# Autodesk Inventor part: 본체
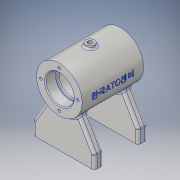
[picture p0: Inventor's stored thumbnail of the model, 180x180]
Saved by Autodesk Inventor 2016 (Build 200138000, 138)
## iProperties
Created: 2018-05
Part Number: 본체
Material: 알루미늄 6061
Document SubType Name: Modeling
Designer: USER
Density: 2.7 g/cm^3
Appearance: 알루미늄 - 평지
Mass: 317.681 g
Surface Area: 375.828 cm^2
Volume: 117.66 cm^3
Author: USER
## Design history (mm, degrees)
sketch "스케치1"
  geometry: L1 (0, 35)-(0, -35); L2 (26, 35)-(26, -35); L3 (26, -35)-(16, -35); L4 (16, -35)-(16, -23); L5 (16, -23)-(14, -23); L6 (14, -23)-(14, -21); L7 (14, -21)-(21, -21); L8 (21, -21)-(21, 21); L9 (21, 21)-(14, 21); L10 (14, 21)-(14, 23); L11 (14, 23)-(16, 23); L12 (16, 23)-(16, 35); L13 (16, 35)-(26, 35); 2 further points
  constraints: 26 end point, 9 perpendicular, 6 point on line, 2 vertical, 1 coincident, 1 midpoint
  dimensions: "d0" = 70 distance of L1.start L1.end; "d2" = 52 diameter of L2 L1; "d3" = 32 diameter of L12 L1; "d4" = 28 diameter of L10 L1; "d5" = 42 diameter of L8 L1; "d6" = 12 distance between parallel lines of L11 L13; "d7" = 12 distance between parallel lines of L3 L5; "d8" = 42 distance between parallel lines of L7 L9; "d9" = 2 distance between parallel lines of L9 L11
revolve "회전1" sketch "스케치1" stored, may be unused: angle "d10" = 90 deg
node "작업 평면1"
sketch "스케치2"
  geometry: L1 (-26, -35)-(26, -35) reference; L2 (-26, 35)-(26, 35) reference; C1 r 5 at (0, 0); 1 further point
  constraints: 1 centre point, 1 coincident
  dimensions: "d12" = 10 diameter of C1
extrude "돌출1" join sketch "스케치2" stored distance "d13" = 10; taper "d14" = 0 deg
sketch "스케치3"
  geometry: C1 r 5 at (0, 0) reference; 1 further point
  constraints: 1 coincident
hole "구멍1" sketch "스케치3" at (0, 0) diameter "d15" = 5.188; stored, may be unused: countersink angle "d19" = 90 deg, drill point angle "d21" = 118 deg; dims "d16" = 12, "d17" = 4, "d18" = 2, "d20" = 16
sketch "스케치4"
  geometry: L1 (0, 0)-(-9.919, -27.251); L2 (0, 0)-(29, 0); C1 r 26 at (0, 0) reference; 1 further point
  constraints: 4 end point, 1 equal length, 1 horizontal
  dimensions: "d22" = 29 distance of L1.start L1.end; "d23" = 110 deg angle of L1 L2
node "작업 평면2"
sketch "스케치5"
  geometry: C1 r 6 at (0, 0); 2 further points
  constraints: 1 centre point, 1 coincident
  dimensions: "d24" = 12 diameter of C1
extrude "돌출2" join sketch "스케치5" stored distance "d25" = 10; taper "d26" = 0 deg
sketch "스케치6"
  geometry: C1 r 6 at (0, 0) reference; 1 further point
  constraints: 1 coincident
hole "구멍2" sketch "스케치6" at (0, 0) diameter "d27" = 5.188; stored, may be unused: countersink angle "d31" = 90 deg, drill point angle "d33" = 118 deg; dims "d28" = 12, "d29" = 4, "d30" = 2, "d32" = 16
node "작업 평면3"
sketch "스케치7"
  geometry: L1 (-35, -65)-(35, -65); L2 (-35, -65)-(-35, -50); L3 (35, -65)-(35, -50); L4 (35, -50)-(17.325, -19.386); L5 (-35, -50)-(-17.325, -19.386); L6 (-35, -50)-(5.727, -50); A1 r 26 centre (0, 0) between (-17.325, -19.386) and (17.325, -19.386) reference; A2 r 26 centre (0, 0) between (-17.325, -19.386) and (17.325, -19.386); 2 further points
  constraints: 12 end point, 4 point on circle, 2 horizontal, 2 vertical, 1 centre point, 1 concentric, 1 midpoint, 1 vertical alignment
  dimensions: "d35" = 70 distance of L1.start L1.end; "d36" = 15 distance of L1.start L2.end; "d37" = 15 distance of L1.end L3.end; "d38" = 150 deg angle of L4 L3; "d39" = 60 deg angle of L6 L5; "d40" = 65 distance from line of point (0, 0) L1
extrude "돌출3" join sketch "스케치7" distance "d41" = 10; taper "d42" = 0 deg
sketch "스케치8" dims "d43" = 42
  geometry: C1 r 26 at (0, 0) reference; C2 r 16 at (0, 0) reference; 5 further points
  constraints: 2 vertical alignment, 1 coincident, 7 other
  dimensions: "d46" = 360 deg dimension on C1.centre point (0, 21) (derived)
hole "구멍3" sketch "스케치8" at (0, 21), (-21, 0), (0, -21), (21, 0) diameter "d48" = 3.242; stored, may be unused: countersink angle "d52" = 90 deg, drill point angle "d54" = 118 deg; dims "d49" = 8, "d50" = 4, "d51" = 2, "d53" = 10
sketch "스케치11"
  geometry: L1 (0, -60)-(70, -60) reference; L2 (70, -60)-(70, -50) reference; L3 (70, -50)-(0, -50) reference; L4 (0, -60)-(0, -50) reference; 5 further points
  dimensions: "d56" = 50 distance of point (15, -55) point (15, -5); "d57" = 20 horizontal distance of point (15, -55) point (35, -30); "d58" = 20 horizontal distance of point (35, -30) point (55, -55); "d59" = 20 horizontal distance of point (35, -30) point (55, -5); "d60" = 40 distance of point (15, -5) point (55, -5); "d61" = 40 distance of point (15, -55) point (55, -55); "d62" = 50 distance of point (55, -55) point (55, -5); "d63" = 25 vertical distance of point (35, -30) point (15, -5)
hole "구멍4" sketch "스케치11" at (55, -5), (55, -55), (15, -55), (15, -5) diameter "d64" = 4.134; stored, may be unused: countersink angle "d68" = 90 deg, drill point angle "d70" = 118 deg; dims "d65" = 8, "d66" = 4, "d67" = 2, "d69" = 10
chamfer "모따기1" distance "d71" = 1; stored, may be unused: second distance "d72" = 2, angle "d73" = 45 deg
fillet "모깎기1" dims "d74" = 2
fillet "모깎기2" dims "d75" = 0.3
fillet "모깎기3" dims "d76" = 3
fillet "모깎기4" dims "d77" = 3
fillet "모깎기5" dims "d78" = 3
fillet "모깎기6" dims "d79" = 3
node "작업 평면4"
sketch "스케치12"
  geometry: L1 (-26, 35)-(26, 35) reference; L2 (-26, -35)-(26, -35) reference; L3 (26, 35)-(26, -35) reference; L4 (5.151, 24.887)-(5.151, -24.887); L5 (5.151, -24.887)-(-5.151, -24.887); L6 (-5.151, -24.887)-(-5.151, 24.887); L7 (-5.151, 24.887)-(5.151, 24.887); 1 further point
  constraints: 2 other
feature "엠보싱1" sketch "스케치12" dims "d12" = 10, "d83" = 0.5, "d84" = 0
node "솔리드1"
mirror "대칭1"
mirror "대칭2"
node "투영된 루프1"
node "투영된 루프3"
other parameters: "d11" = 29, "d80" = 68
